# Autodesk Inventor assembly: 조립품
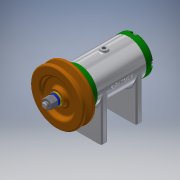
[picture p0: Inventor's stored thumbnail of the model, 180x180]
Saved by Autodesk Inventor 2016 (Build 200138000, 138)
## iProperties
Created: 2020-07
Part Number: 조립품
Material: 일반
Document SubType Name: Assembly
Designer: pc-04
Author: pc-04
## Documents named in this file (15)
- C:\Users\pc-04\Desktop\700706V1016\답안조리품.iam
- C:\Users\pc-04\Desktop\700706V1016\본체.ipt
- C:\Users\pc-04\Desktop\700706V1016\뒤커버.ipt
- C:\Users\pc-04\Desktop\700706V1016\베어링 6002.ipt
- C:\Users\pc-04\Desktop\700706V1016\축.ipt
- C:\Users\pc-04\Desktop\700706V1016\앞커버.ipt
- C:\Users\pc-04\Desktop\700706V1016\키 3x3x12.ipt
- C:\Users\pc-04\Desktop\700706V1016\V벨트풀리.ipt
- C:\Users\pc-04\Desktop\700706V1016\와셔 8x17.ipt
- C:\Users\pc-04\Desktop\700706V1016\스프링와셔 8.ipt
- C:\Users\pc-04\Desktop\700706V1016\너트 M8.ipt
- C:\Users\pc-04\Desktop\700706V1016\오일 실 15 25 7.ipt
- C:\Users\pc-04\Desktop\700706V1016\볼트 M4x12.ipt
- C:\Users\pc-04\Desktop\700706V1016\와셔 6x11.5.ipt
- C:\Users\pc-04\Desktop\700706V1016\볼트 M6x8.ipt
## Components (1 placed, 1 different names)
1. V벨트풀리:1
